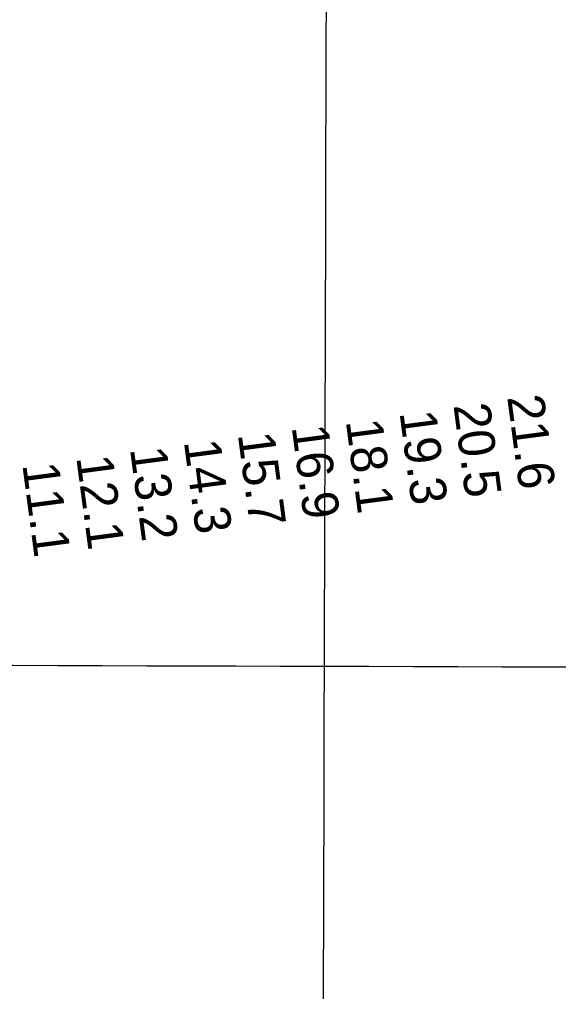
# Model space of a CAD drawing. Extents: x 3161564 to 3199464, y 849354 to 874788.
# Drawn here: x 3175679 to 3176670, y 860252 to 862040 of the extents above; entities that cross this region are included whole.
import ezdxf

# ---------------------------------------------------------------- set-up
doc = ezdxf.new("R2010")
doc.units = 0
for name, color, linetype in [('V-GRID-MAJR', 7, 'Continuous'), ('V-RIVR-RANG', 7, 'Continuous'), ('V-ROAD-CNTR', 7, 'Continuous')]:
    doc.layers.add(name, color=color, linetype=linetype)

msp = doc.modelspace()

# ---------------------------------------------------------------- linework, layer by layer
at = {"layer": 'V-GRID-MAJR'}
for points in [[(3176222.1410000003, 854791.1240000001), (3176239.768, 860850.5530000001), (3176257.404, 866913.068), (3176275.039, 872975.626), (3176275.048, 872978.667)], [(3165780.446, 860882.501), (3171010.106, 860866.147), (3176239.768, 860850.5530000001), (3181469.433, 860835.721), (3186699.099, 860821.649), (3191928.768, 860808.338), (3197158.438, 860795.787), (3197158.4390000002, 860795.787)]]:
    msp.add_spline(points, degree=3, dxfattribs=at)
at = {"layer": 'V-ROAD-CNTR'}
msp.add_spline([(3176879.125204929, 855651.914668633), (3176902.292158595, 855659.0856542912), (3176934.1140949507, 855666.9976384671), (3176983.4499962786, 855657.7056570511), (3177040.651881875, 855639.063694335), (3177110.477742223, 855613.5507453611), (3177170.583622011, 855601.7607689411), (3177236.7824896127, 855586.883798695), (3177274.782413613, 855573.5288254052), (3177317.445328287, 855579.7618129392), (3177362.5952379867, 855595.691781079), (3177411.9501392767, 855643.142686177), (3177451.732059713, 855679.194614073), (3177476.657009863, 855705.7895608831), (3177478.2700066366, 855736.9544985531), (3177464.172034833, 855782.2774079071), (3177430.750101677, 855833.3963056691), (3177372.994217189, 855887.769196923), (3177287.8353875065, 855954.8300628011), (3177219.8185235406, 855998.4419755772), (3177152.9756572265, 856039.3918936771), (3177089.341784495, 856079.2398139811), (3177023.387916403, 856134.3197038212), (3176966.6300299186, 856207.9345565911), (3176895.2451726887, 856290.0793923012), (3176782.2483986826, 856425.1231222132), (3176693.1625768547, 856545.301881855), (3176615.1687328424, 856622.647727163), (3176543.920875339, 856726.504519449), (3176474.3930143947, 856784.205404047), (3176414.352134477, 856823.5773253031), (3176395.899171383, 856827.976316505), (3176350.8212615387, 856806.1753601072), (3176279.148404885, 856754.702463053), (3176211.5535400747, 856707.4195576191), (3176172.2526186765, 856696.1065802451), (3176141.127680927, 856702.011568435), (3176111.749739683, 856719.5775333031), (3176032.565898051, 856777.3694177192), (3175933.5790960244, 856857.4342575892), (3175839.0062851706, 856930.2601119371), (3175807.1383489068, 856951.5090694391), (3175770.0914230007, 856958.6680551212), (3175787.1193889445, 856991.3959896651), (3175795.0863730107, 857040.6808910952), (3175799.484364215, 857113.7327449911), (3175810.823341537, 857206.9175586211), (3175813.712335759, 857287.3653977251), (3175807.7513476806, 857386.8311987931), (3175805.684351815, 857497.9369765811), (3175801.940359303, 857543.6058852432), (3175783.4633962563, 857620.527731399), (3175760.235442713, 857716.1135402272), (3175755.326452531, 857765.5174414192), (3175754.5264541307, 857815.6403411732), (3175751.6894598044, 857884.276203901), (3175756.309450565, 858015.455941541), (3175754.854453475, 858158.5586553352), (3175753.0504570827, 858270.798430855), (3175748.5974659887, 858321.6503291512), (3175736.501490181, 858372.0042284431), (3175677.161608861, 858555.5318613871), (3175602.2427586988, 858747.092478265), (3175558.2188467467, 858866.8562387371), (3175502.5159581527, 858986.2220000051), (3175436.2770906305, 859092.6197872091), (3175371.236220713, 859185.1206022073), (3175300.6823618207, 859261.5774492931), (3175219.099524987, 859367.2332379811), (3175166.218630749, 859443.6520851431), (3175175.325612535, 859507.1279581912), (3175222.0015191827, 859537.876896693), (3175285.3383925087, 859568.346835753), (3175321.1713208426, 859607.463757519), (3175310.2993425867, 859667.2116380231), (3175262.407438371, 859798.6233751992), (3175224.637513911, 859877.8702167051), (3175174.7256137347, 859982.0350083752), (3175144.840673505, 860115.364741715), (3175122.609717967, 860284.7894028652), (3175088.432786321, 860568.568835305), (3175086.2807906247, 860704.5445633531), (3175072.201818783, 860854.517263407), (3175052.526858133, 860999.933972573), (3175047.503868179, 861166.800638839), (3175053.177856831, 861343.7312849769), (3175066.700829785, 861550.381871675), (3175065.4638322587, 861662.491647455), (3175040.178882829, 861767.7534369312), (3175017.8369275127, 861884.1612041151), (3175008.363946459, 862033.901904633), (3174979.613003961, 862160.277651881), (3174952.1400589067, 862274.6484231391), (3174921.634119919, 862422.8161268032), (3174896.957169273, 862525.547921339), (3174861.7462396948, 862663.2186459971), (3174841.1032809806, 862738.0144964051)], degree=3, dxfattribs=at)

# ---------------------------------------------------------------- texts
at = {"layer": 'V-RIVR-RANG'}
for s, p in [('21.6', (3176575.6011061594, 861345.491105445)), ('20.5', (3176476.7370221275, 861330.3175648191)), ('19.3', (3176377.631022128, 861316.9755648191)), ('16.9', (3176179.384462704, 861290.5530706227)), ('18.1', (3176278.8360569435, 861301.2800125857)), ('15.7', (3176080.3140221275, 861276.9495648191)), ('13.2', (3175882.1020221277, 861250.2655648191)), ('14.3', (3175981.208022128, 861263.6075648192)), ('12.1', (3175783.3070569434, 861234.5700125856)), ('11.1', (3175684.2010569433, 861221.2280125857))]:
    msp.add_text(s, height=67.00000000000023, rotation=277.52832571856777, dxfattribs=at).set_placement(p)

doc.saveas('drawing.dxf')
